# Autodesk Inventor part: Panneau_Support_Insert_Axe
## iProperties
Created: 2009-01
Part Number: Panneau_Support_Insert_Axe
Document SubType Name: Modeling
Designer: claivier
Author: claivier
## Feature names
1. Extrusion1
